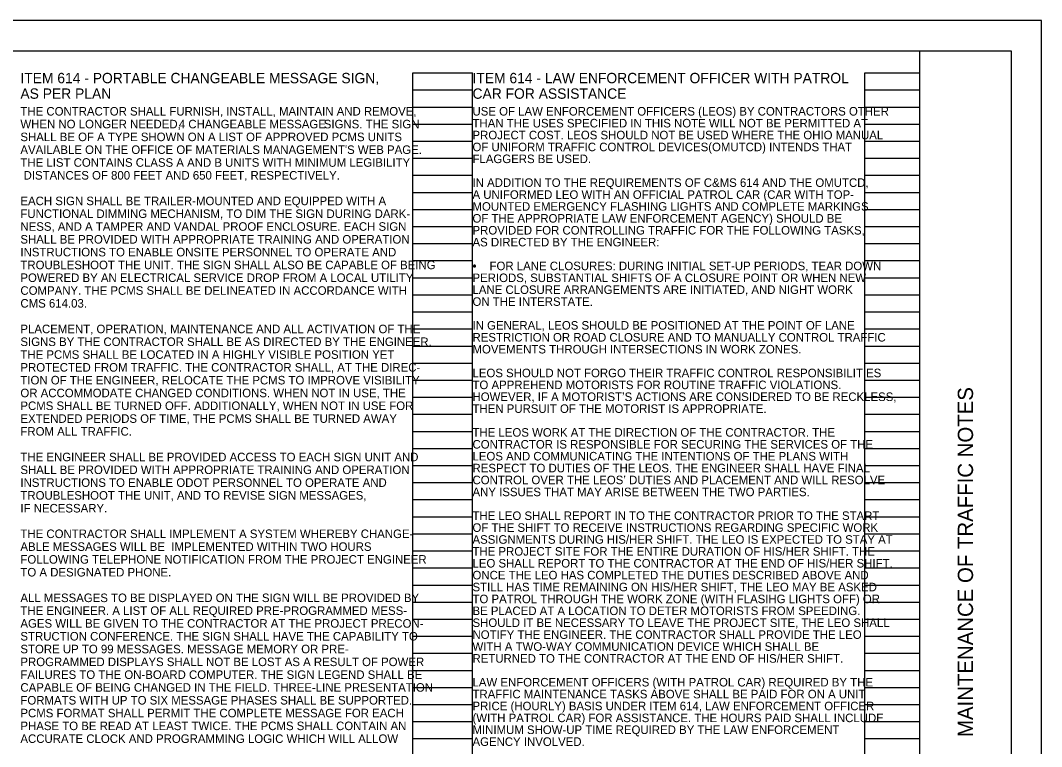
# Model space of a CAD drawing. Extents: x 0 to 34, y 0 to 22.
# Drawn here: x 17.24 to 34, y 10.09 to 22 of the extents above; entities that cross this region are included whole.
import ezdxf

# ---------------------------------------------------------------- set-up
doc = ezdxf.new("R2010")
doc.units = 0
for name, color, linetype in [('SH_Border', 7, 'Continuous'), ('SH_Cut_Line', 7, 'Continuous'), ('SH_Data', 7, 'Continuous'), ('SH_Text', 7, 'Continuous')]:
    doc.layers.add(name, color=color, linetype=linetype)

msp = doc.modelspace()

# ---------------------------------------------------------------- linework, layer by layer
at = {"layer": 'SH_Border'}
msp.add_line((32, 0.5), (32, 21.5), dxfattribs=at)
msp.add_lwpolyline([(1.5, 21.5), (33.5, 21.5), (33.5, 0.5), (1.5, 0.5)], close=True, dxfattribs=at)
at = {"layer": 'SH_Cut_Line'}
msp.add_lwpolyline([(0, 0), (34, 0), (34, 22), (0, 22)], close=True, dxfattribs=at)
at = {"layer": 'SH_Data'}
for p, q in [((23.68, 0.98), (23.68, 21.14)), ((23.68, 21.14), (24.66, 21.14)), ((24.66, 0.98), (24.66, 21.14)), ((31.1, 0.98), (31.1, 21.14)), ((31.1, 21.14), (32, 21.14)), ((32, 0.98), (32, 21.14)), ((23.68, 20.86), (24.66, 20.86)), ((31.1, 20.86), (32, 20.86)), ((23.68, 20.58), (24.66, 20.58)), ((31.1, 20.58), (32, 20.58)), ((23.68, 20.3), (24.66, 20.3)), ((31.1, 20.3), (32, 20.3)), ((23.68, 20.02), (24.66, 20.02)), ((31.1, 20.02), (32, 20.02)), ((23.68, 19.74), (24.66, 19.74)), ((31.1, 19.74), (32, 19.74)), ((23.68, 19.46), (24.66, 19.46)), ((31.1, 19.46), (32, 19.46)), ((23.68, 19.18), (24.66, 19.18)), ((31.1, 19.18), (32, 19.18)), ((23.68, 18.9), (24.66, 18.9)), ((31.1, 18.9), (32, 18.9)), ((23.68, 18.62), (24.66, 18.62)), ((31.1, 18.62), (32, 18.62)), ((23.68, 18.34), (24.66, 18.34)), ((31.1, 18.34), (32, 18.34)), ((23.68, 18.06), (24.66, 18.06)), ((31.1, 18.06), (32, 18.06)), ((23.68, 17.78), (24.66, 17.78)), ((31.1, 17.78), (32, 17.78)), ((23.68, 17.5), (24.66, 17.5)), ((31.1, 17.5), (32, 17.5)), ((23.68, 17.22), (24.66, 17.22)), ((31.1, 17.22), (32, 17.22)), ((23.68, 16.94), (24.66, 16.94)), ((31.1, 16.94), (32, 16.94)), ((23.68, 16.66), (24.66, 16.66)), ((31.1, 16.66), (32, 16.66)), ((23.68, 16.38), (24.66, 16.38)), ((31.1, 16.38), (32, 16.38)), ((23.68, 16.1), (24.66, 16.1)), ((31.1, 16.1), (32, 16.1)), ((23.68, 15.82), (24.66, 15.82)), ((31.1, 15.82), (32, 15.82)), ((23.68, 15.54), (24.66, 15.54)), ((31.1, 15.54), (32, 15.54)), ((23.68, 15.26), (24.66, 15.26)), ((31.1, 15.26), (32, 15.26)), ((23.68, 14.98), (24.66, 14.98)), ((31.1, 14.98), (32, 14.98)), ((23.68, 14.7), (24.66, 14.7)), ((31.1, 14.7), (32, 14.7)), ((23.68, 14.42), (24.66, 14.42)), ((31.1, 14.42), (32, 14.42)), ((23.68, 14.14), (24.66, 14.14)), ((31.1, 14.14), (32, 14.14)), ((23.68, 13.86), (24.66, 13.86)), ((31.1, 13.86), (32, 13.86)), ((23.68, 13.58), (24.66, 13.58)), ((31.1, 13.58), (32, 13.58)), ((23.68, 13.3), (24.66, 13.3)), ((31.1, 13.3), (32, 13.3)), ((23.68, 13.02), (24.66, 13.02)), ((31.1, 13.02), (32, 13.02)), ((23.68, 12.74), (24.66, 12.74)), ((31.1, 12.74), (32, 12.74)), ((23.68, 12.46), (24.66, 12.46)), ((31.1, 12.46), (32, 12.46)), ((23.68, 12.18), (24.66, 12.18)), ((31.1, 12.18), (32, 12.18)), ((23.68, 11.9), (24.66, 11.9)), ((31.1, 11.9), (32, 11.9)), ((23.68, 11.62), (24.66, 11.62)), ((31.1, 11.62), (32, 11.62)), ((23.68, 11.34), (24.66, 11.34)), ((31.1, 11.34), (32, 11.34)), ((23.68, 11.06), (24.66, 11.06)), ((31.1, 11.06), (32, 11.06)), ((23.68, 10.78), (24.66, 10.78)), ((31.1, 10.78), (32, 10.78)), ((23.68, 10.5), (24.66, 10.5)), ((31.1, 10.5), (32, 10.5)), ((23.68, 10.22), (24.66, 10.22)), ((31.1, 10.22), (32, 10.22))]:
    msp.add_line(p, q, dxfattribs=at)

# ---------------------------------------------------------------- texts
msp.add_text('MAINTENANCE OF TRAFFIC NOTES', height=0.25, rotation=90, dxfattribs=at).set_placement((32.875, 10.247))
at = {"layer": 'SH_Text'}
for s, height, p in [('ITEM 614 - PORTABLE CHANGEABLE MESSAGE SIGN, ', 0.17, (17.24, 20.97)), ('ITEM 614 - LAW ENFORCEMENT OFFICER WITH PATROL ', 0.17, (24.66, 20.97)), ('AS PER PLAN', 0.17, (17.24, 20.715)), ('CAR FOR ASSISTANCE', 0.17, (24.66, 20.715)), ('THE CONTRACTOR SHALL FURNISH, INSTALL, MAINTAIN AND REMOVE, ', 0.14, (17.24, 20.44)), ('USE OF LAW ENFORCEMENT OFFICERS (LEOS) BY CONTRACTORS OTHER ', 0.14, (24.66, 20.44)), ('WHEN NO LONGER NEEDED, ', 0.14, (17.24, 20.23)), ('4 CHANGEABLE MESSAGE', 0.14, (19.84, 20.23)), (' SIGNS. THE SIGN ', 0.14, (22.167, 20.23)), ('THAN THE USES SPECIFIED IN THIS NOTE WILL NOT BE PERMITTED AT ', 0.14, (24.66, 20.245)), ('SHALL BE OF A TYPE SHOWN ON A LIST OF APPROVED PCMS UNITS ', 0.14, (17.24, 20.02)), ('PROJECT COST. LEOS SHOULD NOT BE USED WHERE THE OHIO MANUAL ', 0.14, (24.66, 20.05)), ("AVAILABLE ON THE OFFICE OF MATERIALS MANAGEMENT'S WEB PAGE. ", 0.14, (17.24, 19.81)), ('OF UNIFORM TRAFFIC CONTROL DEVICES(OMUTCD) INTENDS THAT ', 0.14, (24.66, 19.855)), ('FLAGGERS BE USED.', 0.14, (24.66, 19.66)), ('THE LIST CONTAINS CLASS A AND B UNITS WITH MINIMUM LEGIBILITY', 0.14, (17.24, 19.6)), (' DISTANCES OF 800 FEET AND 650 FEET, RESPECTIVELY.', 0.14, (17.24, 19.39)), ('IN ADDITION TO THE REQUIREMENTS OF C&MS 614 AND THE OMUTCD, ', 0.14, (24.66, 19.27)), ('EACH SIGN SHALL BE TRAILER-MOUNTED AND EQUIPPED WITH A ', 0.14, (17.24, 18.97)), ('A UNIFORMED LEO WITH AN OFFICIAL PATROL CAR (CAR WITH TOP-', 0.14, (24.66, 19.074)), ('MOUNTED EMERGENCY FLASHING LIGHTS AND COMPLETE MARKINGS ', 0.14, (24.66, 18.879)), ('FUNCTIONAL DIMMING MECHANISM, TO DIM THE SIGN DURING DARK-', 0.14, (17.24, 18.76)), ('OF THE APPROPRIATE LAW ENFORCEMENT AGENCY) SHOULD BE ', 0.14, (24.66, 18.684)), ('NESS, AND A TAMPER AND VANDAL PROOF ENCLOSURE. EACH SIGN ', 0.14, (17.24, 18.55)), ('PROVIDED FOR CONTROLLING TRAFFIC FOR THE FOLLOWING TASKS, ', 0.14, (24.66, 18.489)), ('SHALL BE PROVIDED WITH APPROPRIATE TRAINING AND OPERATION ', 0.14, (17.24, 18.34)), ('AS DIRECTED BY THE ENGINEER:', 0.14, (24.66, 18.294)), ('INSTRUCTIONS TO ENABLE ONSITE PERSONNEL TO OPERATE AND ', 0.14, (17.24, 18.13)), ('TROUBLESHOOT THE UNIT. THE SIGN SHALL ALSO BE CAPABLE OF BEING ', 0.14, (17.24, 17.92)), ('•', 0.14, (24.66, 17.904)), ('FOR LANE CLOSURES: DURING INITIAL SET-UP PERIODS, TEAR DOWN ', 0.14, (24.94, 17.904)), ('POWERED BY AN ELECTRICAL SERVICE DROP FROM A LOCAL UTILITY ', 0.14, (17.24, 17.71)), ('PERIODS, SUBSTANTIAL SHIFTS OF A CLOSURE POINT OR WHEN NEW ', 0.14, (24.66, 17.709)), ('COMPANY. THE PCMS SHALL BE DELINEATED IN ACCORDANCE WITH ', 0.14, (17.24, 17.5)), ('LANE CLOSURE ARRANGEMENTS ARE INITIATED, AND NIGHT WORK ', 0.14, (24.66, 17.514)), ('CMS 614.03.', 0.14, (17.24, 17.29)), ('ON THE INTERSTATE.', 0.14, (24.66, 17.319)), ('PLACEMENT, OPERATION, MAINTENANCE AND ALL ACTIVATION OF THE ', 0.14, (17.24, 16.87)), ('IN GENERAL, LEOS SHOULD BE POSITIONED AT THE POINT OF LANE ', 0.14, (24.66, 16.929)), ('SIGNS BY THE CONTRACTOR SHALL BE AS DIRECTED BY THE ENGINEER. ', 0.14, (17.24, 16.66)), ('RESTRICTION OR ROAD CLOSURE AND TO MANUALLY CONTROL TRAFFIC ', 0.14, (24.66, 16.733)), ('MOVEMENTS THROUGH INTERSECTIONS IN WORK ZONES.', 0.14, (24.66, 16.538)), ('THE PCMS SHALL BE LOCATED IN A HIGHLY VISIBLE POSITION YET ', 0.14, (17.24, 16.45)), ('PROTECTED FROM TRAFFIC. THE CONTRACTOR SHALL, AT THE DIREC-', 0.14, (17.24, 16.24)), ('LEOS SHOULD NOT FORGO THEIR TRAFFIC CONTROL RESPONSIBILITIES ', 0.14, (24.66, 16.148)), ('TION OF THE ENGINEER, RELOCATE THE PCMS TO IMPROVE VISIBILITY ', 0.14, (17.24, 16.03)), ('TO APPREHEND MOTORISTS FOR ROUTINE TRAFFIC VIOLATIONS. ', 0.14, (24.66, 15.953)), ('OR ACCOMMODATE CHANGED CONDITIONS. WHEN NOT IN USE, THE ', 0.14, (17.24, 15.82)), ('HOWEVER, IF A MOTORIST’S ACTIONS ARE CONSIDERED TO BE RECKLESS, ', 0.14, (24.66, 15.758)), ('PCMS SHALL BE TURNED OFF. ADDITIONALLY, WHEN NOT IN USE FOR ', 0.14, (17.24, 15.61)), ('THEN PURSUIT OF THE MOTORIST IS APPROPRIATE.', 0.14, (24.66, 15.563)), ('EXTENDED PERIODS OF TIME, THE PCMS SHALL BE TURNED AWAY ', 0.14, (17.24, 15.4)), ('FROM ALL TRAFFIC.', 0.14, (17.24, 15.19)), ('THE LEOS WORK AT THE DIRECTION OF THE CONTRACTOR. THE ', 0.14, (24.66, 15.173)), ('CONTRACTOR IS RESPONSIBLE FOR SECURING THE SERVICES OF THE ', 0.14, (24.66, 14.978)), ('LEOS AND COMMUNICATING THE INTENTIONS OF THE PLANS WITH ', 0.14, (24.66, 14.783)), ('THE ENGINEER SHALL BE PROVIDED ACCESS TO EACH SIGN UNIT AND ', 0.14, (17.24, 14.77)), ('SHALL BE PROVIDED WITH APPROPRIATE TRAINING AND OPERATION ', 0.14, (17.24, 14.56)), ('RESPECT TO DUTIES OF THE LEOS. THE ENGINEER SHALL HAVE FINAL ', 0.14, (24.66, 14.588)), ('INSTRUCTIONS TO ENABLE ODOT PERSONNEL TO OPERATE AND ', 0.14, (17.24, 14.35)), ('CONTROL OVER THE LEOS’ DUTIES AND PLACEMENT AND WILL RESOLVE ', 0.14, (24.66, 14.393)), ('TROUBLESHOOT THE UNIT, AND TO REVISE SIGN MESSAGES, ', 0.14, (17.24, 14.14)), ('ANY ISSUES THAT MAY ARISE BETWEEN THE TWO PARTIES. ', 0.14, (24.66, 14.197)), ('IF NECESSARY.', 0.14, (17.24, 13.93)), ('THE LEO SHALL REPORT IN TO THE CONTRACTOR PRIOR TO THE START ', 0.14, (24.66, 13.807)), ('OF THE SHIFT TO RECEIVE INSTRUCTIONS REGARDING SPECIFIC WORK ', 0.14, (24.66, 13.612)), ('THE CONTRACTOR SHALL IMPLEMENT A SYSTEM WHEREBY CHANGE-', 0.14, (17.24, 13.51)), ('ABLE MESSAGES WILL BE  IMPLEMENTED WITHIN TWO HOURS ', 0.14, (17.24, 13.3)), ('ASSIGNMENTS DURING HIS/HER SHIFT. THE LEO IS EXPECTED TO STAY AT ', 0.14, (24.66, 13.417)), ('THE PROJECT SITE FOR THE ENTIRE DURATION OF HIS/HER SHIFT. THE ', 0.14, (24.66, 13.222)), ('FOLLOWING TELEPHONE NOTIFICATION FROM THE PROJECT ENGINEER ', 0.14, (17.24, 13.09)), ('LEO SHALL REPORT TO THE CONTRACTOR AT THE END OF HIS/HER SHIFT. ', 0.14, (24.66, 13.027)), ('TO A DESIGNATED PHONE.', 0.14, (17.24, 12.88)), ('ONCE THE LEO HAS COMPLETED THE DUTIES DESCRIBED ABOVE AND ', 0.14, (24.66, 12.832)), ('STILL HAS TIME REMAINING ON HIS/HER SHIFT, THE LEO MAY BE ASKED ', 0.14, (24.66, 12.637)), ('ALL MESSAGES TO BE DISPLAYED ON THE SIGN WILL BE PROVIDED BY ', 0.14, (17.24, 12.46)), ('TO PATROL THROUGH THE WORK ZONE (WITH FLASIHG LIGHTS OFF) OR ', 0.14, (24.66, 12.442)), ('THE ENGINEER. A LIST OF ALL REQUIRED PRE-PROGRAMMED MESS-', 0.14, (17.24, 12.25)), ('BE PLACED AT A LOCATION TO DETER MOTORISTS FROM SPEEDING. ', 0.14, (24.66, 12.247)), ('AGES WILL BE GIVEN TO THE CONTRACTOR AT THE PROJECT PRECON-', 0.14, (17.24, 12.04)), ('SHOULD IT BE NECESSARY TO LEAVE THE PROJECT SITE, THE LEO SHALL ', 0.14, (24.66, 12.052)), ('STRUCTION CONFERENCE. THE SIGN SHALL HAVE THE CAPABILITY TO ', 0.14, (17.24, 11.83)), ('NOTIFY THE ENGINEER. THE CONTRACTOR SHALL PROVIDE THE LEO ', 0.14, (24.66, 11.857)), ('STORE UP TO 99 MESSAGES. MESSAGE MEMORY OR PRE-', 0.14, (17.24, 11.62)), ('WITH A TWO-WAY COMMUNICATION DEVICE WHICH SHALL BE ', 0.14, (24.66, 11.661)), ('RETURNED TO THE CONTRACTOR AT THE END OF HIS/HER SHIFT.', 0.14, (24.66, 11.466)), ('PROGRAMMED DISPLAYS SHALL NOT BE LOST AS A RESULT OF POWER ', 0.14, (17.24, 11.41)), ('FAILURES TO THE ON-BOARD COMPUTER. THE SIGN LEGEND SHALL BE ', 0.14, (17.24, 11.2)), ('CAPABLE OF BEING CHANGED IN THE FIELD. THREE-LINE PRESENTATION ', 0.14, (17.24, 10.99)), ('LAW ENFORCEMENT OFFICERS (WITH PATROL CAR) REQUIRED BY THE ', 0.14, (24.66, 11.076)), ('FORMATS WITH UP TO SIX MESSAGE PHASES SHALL BE SUPPORTED.  ', 0.14, (17.24, 10.78)), ('TRAFFIC MAINTENANCE TASKS ABOVE SHALL BE PAID FOR ON A UNIT ', 0.14, (24.66, 10.881)), ('PRICE (HOURLY) BASIS UNDER ITEM 614, LAW ENFORCEMENT OFFICER ', 0.14, (24.66, 10.686)), ('PCMS FORMAT SHALL PERMIT THE COMPLETE MESSAGE FOR EACH ', 0.14, (17.24, 10.57)), ('(WITH PATROL CAR) FOR ASSISTANCE. THE HOURS PAID SHALL INCLUDE ', 0.14, (24.66, 10.491)), ('PHASE TO BE READ AT LEAST TWICE. THE PCMS SHALL CONTAIN AN ', 0.14, (17.24, 10.36)), ('MINIMUM SHOW-UP TIME REQUIRED BY THE LAW ENFORCEMENT ', 0.14, (24.66, 10.296)), ('ACCURATE CLOCK AND PROGRAMMING LOGIC WHICH WILL ALLOW ', 0.14, (17.24, 10.15)), ('AGENCY INVOLVED.', 0.14, (24.66, 10.101))]:
    msp.add_text(s, height=height, dxfattribs=at).set_placement(p)

doc.saveas('drawing.dxf')
